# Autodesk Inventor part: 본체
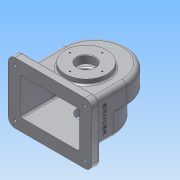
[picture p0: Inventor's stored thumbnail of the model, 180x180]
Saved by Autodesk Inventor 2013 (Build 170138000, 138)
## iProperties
Created: 2017-11
Part Number: 본체
Material: 알루미늄 6061
Document SubType Name: Modeling
Designer: Administrator
Density: 2.71 g/cm^3
Mass: 1079.49 g
Surface Area: 1182.07 cm^2
Volume: 398.335 cm^3
Author: Administrator
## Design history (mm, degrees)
sketch "스케치1"
  geometry: L1 (-58, 0)-(-58, -80); L2 (-58, -80)-(58, -80); L3 (58, -80)-(58, 0); A1 r 58 centre (0, 0) between (58, 0) and (-58, 0); 1 further point
  constraints: 6 end point, 2 point on circle, 2 tangent, 2 vertical, 1 centre point, 1 coincident, 1 horizontal
  dimensions: "d0" = 116 diameter of A1; "d3" = 80 distance from line of point (0, 0) L2
extrude "돌출1" new body sketch "스케치1" distance "d4" = 38; taper "d5" = 0 deg
sketch "스케치4"
  geometry: L1 (-58, 0)-(-58, -80) reference; L2 (-58, -80)-(58, -80) reference; L3 (58, -80)-(58, 0) reference; L4 (-58, -23)-(-58, -80); L5 (-58, -80)-(58, -80); L6 (58, -80)-(58, -23); A1 r 58 centre (0, -23) between (58, -23) and (-58, -23)
  constraints: 6 end point, 2 perpendicular, 2 point on circle, 2 point on line, 1 centre point, 1 tangent
  dimensions: "d12" = 58 radius of A1; "d14" = 57 distance from line of L2 A1.centre
extrude "돌출3" join sketch "스케치4" distance "d15" = 38; taper "d16" = 0 deg
feature "쉘1" dims "d17" = 5
sketch "스케치8"
  geometry: L1 (-58, -80)-(58, -80) reference; C1 r 37.5 at (0, -15); A1 r 58 centre (0, 0) between (58, 0) and (-58, 0) reference
  constraints: 1 centre point, 1 vertical alignment
  dimensions: "d18" = 65 distance from line of L1 C1.centre; "d19" = 75 diameter of C1
extrude "돌출4" join sketch "스케치8" distance "d20" = 9; taper "d21" = 0 deg
sketch "스케치9"
  geometry: L1 (-58, -80)-(58, -80) reference; C1 r 31 at (0, -15); 1 further point
  constraints: 1 centre point, 1 vertical alignment
  dimensions: "d22" = 65 distance from line of L1 C1.centre; "d23" = 62 diameter of C1
extrude "돌출5" join sketch "스케치9" distance "d24" = 10; taper "d25" = 0 deg
sketch "스케치11"
  geometry: L1 (133, 17)-(-17, 17); L2 (-17, 17)-(-17, -93); L3 (-17, -93)-(133, -93); L4 (133, -93)-(133, 17); L5 (133, 17)-(-17, -93); L6 (-17, 17)-(133, -93); L7 (0, -76)-(116, -76); L8 (116, -76)-(116, 0); L9 (116, 0)-(0, 0); L10 (0, 0)-(0, -76); L11 (0, -76)-(116, 0); L12 (116, -76)-(0, 0); 2 further points
  constraints: 24 end point, 5 midpoint, 4 parallel, 2 horizontal, 2 perpendicular
  dimensions: "d26" = 150 distance of L2.end L3.end; "d28" = 110 distance of L3.end L1.start
extrude "돌출6" join sketch "스케치11" distance "d29" = 15; taper "d30" = 0 deg
fillet "모깎기1" dims "d31" = 12
fillet "모깎기2" dims "d32" = 8
node "작업 평면1"
sketch "스케치12"
  geometry: L1 (-113, 93)-(-13, 93) reference; C1 r 6 at (-63, 74); 1 further point
  constraints: 1 centre point, 1 vertical alignment
  dimensions: "d34" = 12 diameter of C1; "d36" = 19 distance from line of C1.centre L1
extrude "돌출7" join sketch "스케치12" stored distance "d37" = 15; taper "d38" = 0 deg
hole "구멍1" diameter "d42" = 4.459; stored, may be unused: countersink angle "d46" = 90 deg, drill point angle "d48" = 118 deg; dims "d43" = 6, "d44" = 4, "d45" = 2, "d47" = 8, "d49" = 10, "d50" = 10
sketch "스케치14"
  geometry: L1 (63, -65)-(-63, -65) reference; C1 r 37.5 at (0, 0) reference; C2 r 16 at (0, 0); 1 further point
  constraints: 1 centre point, 1 coincident
  dimensions: "d52" = 32 diameter of C2
extrude "돌출8" cut sketch "스케치14" stored distance "d54" = 15; taper "d55" = 0 deg
sketch "스케치15" dims "d56" = 58
  geometry: C1 r 16 at (0, 0) reference; C2 r 37.5 at (0, 0) reference; C3 r 1.5 at (0, 29); 2 further points
  constraints: 2 vertical alignment, 1 centre point, 1 coincident, 2 other
  dimensions: "d57" = 3 diameter of C3
hole "구멍2" sketch "스케치15" at (0, 29) diameter "d58" = 2.459; stored, may be unused: countersink angle "d62" = 90 deg, drill point angle "d64" = 118 deg; dims "d59" = 6, "d60" = 4, "d61" = 2, "d63" = 8
sketch "스케치16" dims "d65" = 52
  geometry: C1 r 16 at (0, 0) reference; C2 r 31 at (0, 0) reference; C3 r 1.5 at (0, 26); 2 further points
  constraints: 2 vertical alignment, 1 centre point, 1 coincident, 2 other
  dimensions: "d66" = 3 diameter of C3
hole "구멍3" sketch "스케치16" at (0, 26) diameter "d67" = 2.459; stored, may be unused: countersink angle "d71" = 90 deg, drill point angle "d73" = 118 deg; dims "d68" = 6, "d69" = 4, "d70" = 2, "d72" = 8
sketch "스케치17"
  geometry: A1 r 12 centre (-5, 81) between (-5, 93) and (-17, 81) reference; A2 r 12 centre (-5, -5) between (-17, -5) and (-5, -17) reference; A3 r 12 centre (121, -5) between (121, -17) and (133, -5) reference; A4 r 12 centre (121, 81) between (133, 81) and (121, 93) reference; 1 further point
hole "구멍4" sketch "스케치17" at (-5, 81), (-5, -5), (121, 81), (121, -5) diameter "d77" = 5; stored, may be unused: countersink angle "d81" = 90 deg, drill point angle "d83" = 0 deg; dims "d78" = 6, "d79" = 12, "d80" = 5, "d82" = 8
fillet "모깎기3" dims "d84" = 3
chamfer "모따기1" distance "d85" = 1; stored, may be unused: second distance "d86" = 2, angle "d87" = 45 deg
sketch "스케치18"
  geometry: L1 (-13, -18)-(-25, -18) reference; L2 (-8, 62)-(-8, 0) reference; 2 further points
  constraints: 1 other
  dimensions: "d88" = 40 distance from line of L1 point (30, 22); "d89" = 38 distance from line of point (30, 22) L2
feature "엠보싱1" sketch "스케치18" dims "d90" = 0.5, "d91" = 0
node "솔리드1"
pattern_circular "원형 패턴1" dims angle "d75" = 360 deg
other parameters: "d11" = 116, "d33" = -144
